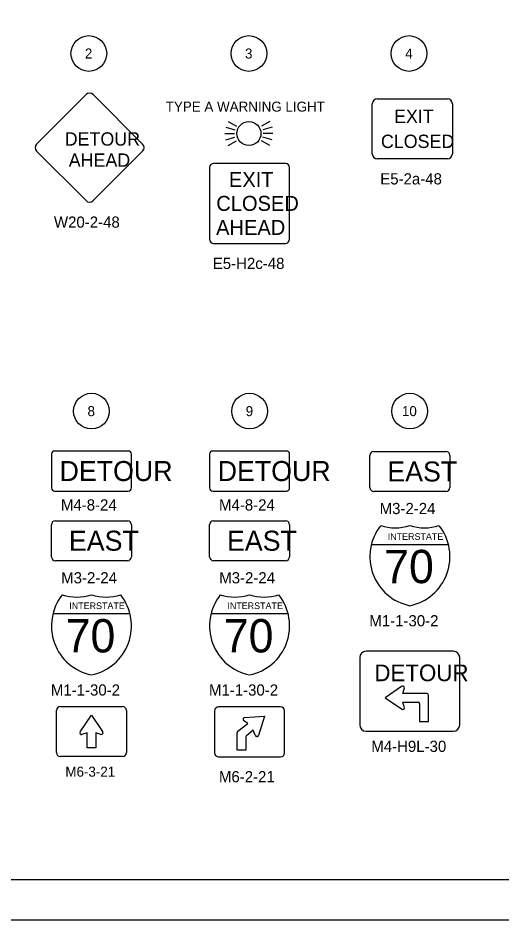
# Model space of a CAD drawing. Extents: x 0 to 680, y 0 to 440.
# Drawn here: x 318.1 to 439, y 0 to 225.4 of the extents above; entities that cross this region are included whole.
import ezdxf

# ---------------------------------------------------------------- set-up
doc = ezdxf.new("R2010")
doc.units = 0
for name, color, linetype in [('GM_X_County', 7, 'Continuous'), ('GM_X_Minor_Lake', 7, 'Continuous'), ('GM_X_Minor_River_Text', 7, 'Continuous'), ('GM_X_State_Shield', 7, 'Continuous'), ('GM_X_Unincorporated_Text', 7, 'Continuous'), ('GM_X_US_Shield', 7, 'Continuous')]:
    doc.layers.add(name, color=color, linetype=linetype)

msp = doc.modelspace()

# ---------------------------------------------------------------- linework, layer by layer
at = {"layer": 'GM_X_County'}
msp.add_lwpolyline([(0, 0), (680, 0), (680, 440), (0, 440)], close=True, dxfattribs=at)
at = {"layer": 'GM_X_Minor_Lake'}
for p, q in [((370.58, 199.57), (372.66, 198.37)), ((380.97, 199.57), (378.89, 198.37)), ((369.78, 196.57), (372.18, 196.57)), ((369.98, 198.12), (372.3, 197.5)), ((381.57, 198.12), (379.25, 197.5)), ((381.78, 196.57), (379.38, 196.57)), ((369.98, 195.02), (372.3, 195.64)), ((370.58, 193.57), (372.66, 194.77)), ((380.97, 193.57), (378.89, 194.77)), ((381.57, 195.02), (379.25, 195.64))]:
    msp.add_line(p, q, dxfattribs=at)
for centre, radius in [((335.78, 216.57), 4.46), ((375.78, 216.57), 4.46), ((415.78, 216.57), 4.46), ((375.78, 196.57), 3), ((336.44, 127.18), 4.46), ((375.94, 127.18), 4.46), ((415.96, 127.18), 4.46)]:
    msp.add_circle(centre, radius, dxfattribs=at)
at = {"layer": 'GM_X_Minor_River_Text'}
msp.add_lwpolyline([(30, 430), (670, 430), (670, 10), (30, 10)], close=True, dxfattribs=at)
at = {"layer": 'GM_X_Unincorporated_Text'}
for p, q in [((365.93, 188.07), (365.93, 170.15)), ((384.89, 189.11), (366.97, 189.11)), ((385.93, 170.15), (385.93, 188.07)), ((366.97, 169.11), (384.89, 169.11)), ((406, 108.1), (406, 116.1)), ((407, 117.1), (425, 117.1)), ((426, 116.1), (426, 108.1)), ((425, 107.1), (407, 107.1)), ((327.44, 99.79), (345.44, 99.79)), ((366.94, 99.79), (384.94, 99.79)), ((326.44, 90.79), (326.44, 98.79)), ((346.44, 98.79), (346.44, 90.79)), ((365.94, 90.79), (365.94, 98.79)), ((385.94, 98.79), (385.94, 90.79)), ((345.44, 89.79), (327.44, 89.79)), ((384.94, 89.79), (366.94, 89.79)), ((413.91, 58.34), (409.83, 55.54)), ((414.21, 56.63), (414.62, 58.04)), ((420.14, 56.63), (414.21, 56.63)), ((420.14, 56.63), (420.14, 56.63)), ((409.83, 55.54), (413.91, 52.75)), ((414.62, 53.04), (414.21, 54.45)), ((414.21, 54.45), (418.11, 54.45)), ((418.42, 54.13), (418.42, 49.6)), ((420.61, 49.6), (420.61, 56.17)), ((327.68, 41.85), (327.68, 52.35)), ((328.68, 53.35), (344.18, 53.35)), ((345.18, 52.35), (345.18, 41.85)), ((333.59, 47.02), (336.43, 51.16)), ((336.43, 51.16), (339.23, 47.08)), ((418.42, 49.6), (420.61, 49.6)), ((335.34, 46.79), (334.06, 46.39)), ((335.34, 43.04), (335.34, 46.79)), ((338.81, 46.39), (337.53, 46.79)), ((337.53, 46.79), (337.53, 43.04)), ((337.53, 43.04), (335.34, 43.04)), ((344.18, 40.85), (328.68, 40.85))]:
    msp.add_line(p, q, dxfattribs=at)
for points in [[(322.7, 193.94), (335.08, 206.31)], [(336.84, 206.31), (349.22, 193.94)], [(407.86, 205.24), (425.36, 205.24)], [(406.61, 191.49), (406.61, 203.99)], [(426.61, 203.99), (426.61, 191.49)], [(335.08, 179.8), (322.7, 192.17)], [(349.22, 192.17), (336.84, 179.8)], [(425.36, 190.24), (407.86, 190.24)], [(326.44, 116.41), (326.44, 108.01)], [(345.64, 117.21), (327.24, 117.21)], [(346.44, 108.01), (346.44, 116.41)], [(365.94, 116.41), (365.94, 108.01)], [(385.14, 117.21), (366.74, 117.21)], [(385.94, 108.01), (385.94, 116.41)], [(327.24, 107.21), (345.64, 107.21)], [(366.74, 107.21), (385.14, 107.21)], [(403.47, 65.58), (403.47, 48.78)], [(426.87, 67.18), (405.07, 67.18)], [(428.47, 48.78), (428.47, 65.58)], [(405.07, 47.18), (426.87, 47.18)]]:
    msp.add_lwpolyline(points, dxfattribs=at)
for centre, radius, start, end in [((335.96, 205.43), 1.25, 45, 135), ((407.86, 203.99), 1.25, 90, 180), ((425.36, 203.99), 1.25, 0, 90), ((323.59, 193.05), 1.25, 135, 225), ((348.33, 193.05), 1.25, 315, 45), ((407.86, 191.49), 1.25, 180, 270), ((425.36, 191.49), 1.25, 270, 0), ((366.97, 188.07), 1.04, 90, 180), ((384.89, 188.07), 1.04, 0, 90), ((335.96, 180.68), 1.25, 225, 315), ((366.97, 170.15), 1.04, 180, 270), ((384.89, 170.15), 1.04, 270, 0), ((327.24, 116.41), 0.8, 90, 180), ((345.64, 116.41), 0.8, 360, 90), ((366.74, 116.41), 0.8, 90, 180), ((385.14, 116.41), 0.8, 360, 90), ((407, 116.1), 1, 90, 180), ((425, 116.1), 1, 360, 90), ((327.24, 108.01), 0.8, 180, 270), ((345.64, 108.01), 0.8, 270, 360), ((366.74, 108.01), 0.8, 180, 270), ((385.14, 108.01), 0.8, 270, 360), ((407, 108.1), 1, 180, 270), ((425, 108.1), 1, 270, 360), ((327.44, 98.79), 1, 90, 180), ((345.44, 98.79), 1, 360, 90), ((366.94, 98.79), 1, 90, 180), ((384.94, 98.79), 1, 360, 90), ((327.44, 90.79), 1, 180, 270), ((345.44, 90.79), 1, 270, 360), ((366.94, 90.79), 1, 180, 270), ((384.94, 90.79), 1, 270, 360), ((405.07, 65.58), 1.6, 90, 180), ((426.87, 65.58), 1.6, 360, 90), ((414.21, 58.04), 0.417, 0.0017, 134.9999), ((420.14, 56.16), 0.469, 0, 90), ((418.11, 54.13), 0.312, 0, 90), ((328.68, 52.35), 1, 90, 180), ((344.18, 52.35), 1, 0, 90), ((414.21, 53.04), 0.417, 225.0001, 0.0017), ((405.07, 48.78), 1.6, 180, 270), ((426.87, 48.78), 1.6, 270, 360), ((333.93, 46.79), 0.417, 145.4112, 287.2046), ((338.93, 46.79), 0.417, 252.7954, 45.0096), ((328.68, 41.85), 1, 180, 270), ((344.18, 41.85), 1, 270, 0)]:
    msp.add_arc(centre, radius, start, end, dxfattribs=at)
at = {"layer": 'GM_X_US_Shield'}
for p, q in [((406.39, 93.87), (425.62, 93.87)), ((326.82, 76.56), (346.06, 76.56)), ((366.32, 76.56), (385.56, 76.56)), ((367.2, 52.26), (367.2, 41.76)), ((383.7, 53.26), (368.2, 53.26)), ((384.7, 41.76), (384.7, 52.26)), ((375.53, 49.12), (374.42, 49.88)), ((374.69, 50.59), (379.7, 50.9)), ((374.69, 50.59), (374.69, 50.59)), ((379.7, 50.9), (378.19, 46.11)), ((373.01, 47.15), (375.53, 49.12)), ((376.88, 47.4), (375.14, 46.03)), ((377.38, 46.23), (376.88, 47.4)), ((372.83, 42.48), (372.83, 46.78)), ((375.01, 45.78), (375.01, 42.48)), ((368.2, 40.76), (383.7, 40.76)), ((375.01, 42.48), (372.83, 42.48))]:
    msp.add_line(p, q, dxfattribs=at)
for centre, radius, start, end in [((418.5, 90.8), 12.5, 141.669, 258.463), ((412.35, 110.51), 12.5, 253.0091, 286.9909), ((419.66, 110.51), 12.5, 253.0091, 286.9909), ((413.5, 90.8), 12.5, 281.537, 38.331), ((338.94, 73.49), 12.5, 141.669, 258.463), ((332.78, 93.2), 12.5, 253.0091, 286.9909), ((340.09, 93.2), 12.5, 253.0091, 286.9909), ((333.94, 73.49), 12.5, 281.537, 38.331), ((378.44, 73.49), 12.5, 141.669, 258.463), ((372.29, 93.2), 12.5, 253.0091, 286.9909), ((379.59, 93.2), 12.5, 253.0091, 286.9909), ((373.44, 73.49), 12.5, 281.537, 38.331), ((368.2, 52.26), 1, 90, 180), ((383.7, 52.26), 1, 0, 90), ((374.72, 50.17), 0.417, 93.5999, 225.0001), ((373.3, 46.78), 0.468, 127.7857, 180), ((375.33, 45.78), 0.312, 127.3494, 180), ((377.79, 46.23), 0.417, 180.0509, 342.5804), ((368.2, 41.76), 1, 180, 270), ((383.7, 41.76), 1, 270, 360)]:
    msp.add_arc(centre, radius, start, end, dxfattribs=at)

# ---------------------------------------------------------------- texts
at = {"layer": 'GM_X_Minor_Lake'}
for s, p in [('2', (334.8, 215.32)), ('3', (374.8, 215.32)), ('4', (414.83, 215.32)), ('8', (335.45, 125.93)), ('9', (374.98, 125.93)), ('10', (414.01, 125.93))]:
    msp.add_text(s, height=2.5, dxfattribs=at).set_placement(p)
at = {"layer": 'GM_X_State_Shield'}
for s, height, p in [('TYPE A WARNING LIGHT', 2.5, (355, 202.04)), ('E5-2a-48', 2.8, (408.59, 183.84)), ('W20-2-48', 2.8, (327.07, 173.03)), ('E5-H2c-48', 2.8, (366.76, 162.71)), ('M4-8-24', 2.8, (328.81, 102.34)), ('M4-8-24', 2.8, (368.31, 102.34)), ('M3-2-24', 2.8, (408.44, 101.44)), ('M3-2-24', 2.8, (328.87, 84.13)), ('M3-2-24', 2.8, (368.37, 84.13)), ('M1-1-30-2', 2.8, (405.87, 73.39)), ('M1-1-30-2', 2.8, (326.3, 56.08)), ('M1-1-30-2', 2.8, (365.8, 56.08)), ('M4-H9L-30', 2.8, (406.35, 42)), ('M6-3-21', 2.5, (329.92, 35.81)), ('M6-2-21', 2.8, (368.29, 34.41))]:
    msp.add_text(s, height=height, dxfattribs=at).set_placement(p)
at = {"layer": 'GM_X_Unincorporated_Text'}
for s, height, p in [('EXIT', 3.333, (412.04, 199.2)), ('DETOUR', 3.333, (329.76, 193.54)), ('CLOSED', 3.333, (408.76, 192.95)), ('AHEAD', 3.333, (330.76, 188.26)), ('EXIT', 3.75, (370.79, 183.18)), ('CLOSED', 3.75, (367.63, 177.24)), ('AHEAD', 3.75, (367.58, 171.22)), ('DETOUR', 5, (328.47, 109.71)), ('DETOUR', 5, (367.97, 109.71)), ('EAST', 5, (410.36, 109.6)), ('EAST', 5, (330.8, 92.29)), ('EAST', 5, (370.3, 92.29)), ('DETOUR', 4.167, (407.12, 59.68)), ('DETOUR', 4.167, (407.12, 59.68))]:
    msp.add_text(s, height=height, dxfattribs=at).set_placement(p)
at = {"layer": 'GM_X_US_Shield'}
for s, height, p in [('INTERSTATE', 1.667, (410.46, 95.01)), ('70', 8.333, (409.58, 84.18)), ('INTERSTATE', 1.667, (330.9, 77.7)), ('INTERSTATE', 1.667, (370.4, 77.7)), ('70', 8.333, (330.01, 66.87)), ('70', 8.333, (369.51, 66.87))]:
    msp.add_text(s, height=height, dxfattribs=at).set_placement(p)

doc.saveas('drawing.dxf')
